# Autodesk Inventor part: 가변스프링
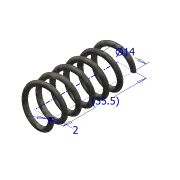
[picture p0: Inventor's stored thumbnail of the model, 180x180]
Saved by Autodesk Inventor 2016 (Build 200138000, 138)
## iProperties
Created: 2020-02
Part Number: 가변스프링
Material: 강철
Document SubType Name: Modeling
Designer: Administrator
Density: 7.85 g/cm^3
Appearance: 플레이트
Mass: 6.42998 g
Surface Area: 16.6202 cm^2
Volume: 0.819106 cm^3
Author: Administrator
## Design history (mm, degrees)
sketch "스케치1"
  geometry: L1 (0, 0)-(7, 0); L2 (7, 0)-(7, 35.5); L3 (7, 35.5)-(0, 35.5); L4 (0, 35.5)-(0, 0); C1 r 1 at (7, 0)
  constraints: 8 end point, 2 parallel, 1 centre point, 1 coincident, 1 horizontal, 1 perpendicular
  dimensions: "d0" = 2 diameter of C1; "d1" = 35.5 distance of L1.end L2.end (derived); "d2" = 14 diameter of L2 L4
feature "코일1" sketch "스케치1" pitch "d3" = 10; turns "d5" = 6; dims "d4" = 35.5 (= d1), "d6" = 0, angle "d7" = 90 deg, angle "d8" = 90 deg, "d9" = 0, "d10" = 0
sketch "스케치2"
  geometry: L1 (-14.259, 12.495)-(13.827, 12.495); L2 (13.827, 12.495)-(13.827, -10.19); L3 (13.827, -10.19)-(-14.259, -10.19); L4 (-14.259, -10.19)-(-14.259, 12.495); 1 further point
  constraints: 8 end point, 2 parallel, 1 horizontal, 1 perpendicular
extrude "돌출1" cut sketch "스케치2" distance "d11" = 10; taper "d12" = 0 deg
node "작업 평면1"
sketch "스케치3"
  geometry: L1 (-8.556, 12.423)-(20.467, 12.423); L2 (20.467, 12.423)-(20.467, -13.575); L3 (20.467, -13.575)-(-8.556, -13.575); L4 (-8.556, -13.575)-(-8.556, 12.423); 1 further point
  constraints: 8 end point, 2 parallel, 1 horizontal, 1 perpendicular
extrude "돌출2" cut sketch "스케치3" distance "d14" = 10; taper "d15" = 0 deg
node "솔리드1"
other parameters: "d13" = 90 deg
